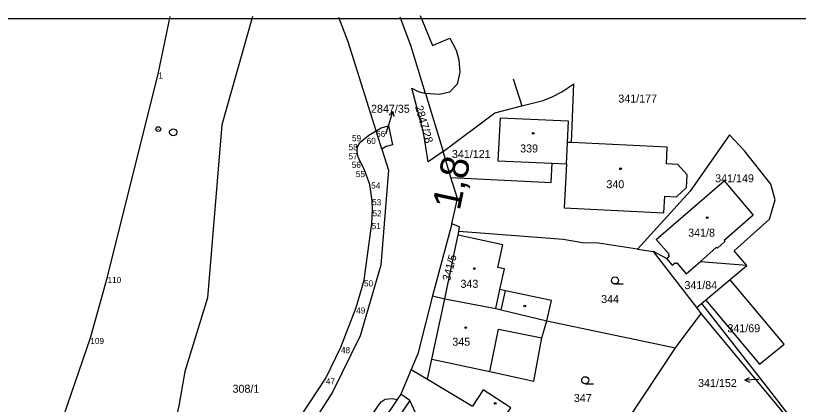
# Model space of a CAD drawing. Extents: x -558358 to -557517, y -1073785 to -1073189.
# Drawn here: x -558075.9 to -557909.7, y -1073271.9 to -1073189.5 of the extents above; entities that cross this region are included whole.
import ezdxf

# ---------------------------------------------------------------- set-up
doc = ezdxf.new("R2010")
doc.units = 0
for name, color, linetype in [('Hranice parcel', 7, 'Continuous'), ('Návěst místo trati', 7, 'Continuous'), ('Parcelní čísla', 7, 'Continuous'), ('Pop  PČ popisy', 7, 'Continuous'), ('Rozpiska_pole_1', 7, 'Continuous'), ('Svazek obcí údolí Desné', 7, 'Continuous'), ('Vnitřní kresba', 7, 'Continuous'), ('Vrstva 60', 7, 'Continuous'), ('Značky budov', 7, 'Continuous'), ('Značky kultur', 7, 'Continuous')]:
    doc.layers.add(name, color=color, linetype=linetype)

msp = doc.modelspace()

# ---------------------------------------------------------------- linework, layer by layer
at = {"layer": 'Hranice parcel'}
for p, q in [((-557970.23, -1073202.86), (-557968.43, -1073208.63)), ((-557957.84, -1073216.4), (-557957.38, -1073203.94)), ((-557990.44, -1073205.56), (-557988.88, -1073205.99)), ((-557988.88, -1073205.99), (-557985.13, -1073218.31)), ((-557985.87, -1073206.17), (-557988.88, -1073205.99)), ((-557974.16, -1073210.07), (-557968.43, -1073208.63)), ((-557985.13, -1073218.31), (-557974.16, -1073210.07)), ((-558000.9, -1073214.81), (-557999.34, -1073213.91)), ((-557999.34, -1073213.91), (-557998.27, -1073213.29)), ((-557998.11, -1073217.81), (-557999.34, -1073213.91)), ((-557924.3, -1073214.73), (-557932.67, -1073226.72)), ((-557997.23, -1073217.21), (-557998.11, -1073217.81)), ((-557958.95, -1073220.92), (-557958.74, -1073216.36)), ((-557957.84, -1073216.4), (-557958.74, -1073216.36)), ((-557985.13, -1073218.31), (-557988.34, -1073220.45)), ((-557983.46, -1073223.81), (-557985.13, -1073218.31)), ((-557961.95, -1073220.78), (-557958.95, -1073220.92)), ((-557932.67, -1073226.72), (-557943.85, -1073239.02)), ((-557983.29, -1073233.62), (-557987.36, -1073248.89)), ((-557981.96, -1073236.04), (-557981.79, -1073235.24)), ((-557943.85, -1073239.02), (-557940.47, -1073239.54)), ((-557931.28, -1073251.41), (-557940.47, -1073239.54)), ((-557937.69, -1073241), (-557940.47, -1073239.54)), ((-557920.64, -1073242.45), (-557930.56, -1073241.68)), ((-557930.24, -1073250.53), (-557920.64, -1073242.45)), ((-557987.36, -1073248.89), (-557984.8, -1073249.54)), ((-557931.28, -1073251.41), (-557930.24, -1073250.53)), ((-557935.78, -1073259.94), (-557930.32, -1073252.64)), ((-557930.32, -1073252.64), (-557931.28, -1073251.41)), ((-557909.08, -1073278.25), (-557930.32, -1073252.64)), ((-557963.13, -1073254.23), (-557935.78, -1073259.94)), ((-557954.2, -1073287.72), (-557935.78, -1073259.94)), ((-557991.89, -1073264.55), (-557994.13, -1073269.82)), ((-557991.89, -1073264.55), (-557988.45, -1073266.61)), ((-557988.45, -1073266.61), (-557978.88, -1073272.32)), ((-557994.86, -1073270.9), (-558022.09, -1073311.21)), ((-557995.96, -1073270.7), (-557994.86, -1073270.9)), ((-557994.13, -1073269.82), (-557994.86, -1073270.9)), ((-557992.18, -1073271.14), (-557994.13, -1073269.82)), ((-557990.25, -1073275.48), (-557992.18, -1073271.14))]:
    msp.add_line(p, q, dxfattribs=at)
for points in [[(-557990.03, -1073189.46), (-557987.35, -1073195.77), (-557983.68, -1073194.26), (-557982.33, -1073196.81), (-557981.76, -1073198.85), (-557981.57, -1073201.43), (-557982.14, -1073203.98), (-557983.75, -1073205.73), (-557985.87, -1073206.17)], [(-557988.88, -1073205.99), (-557991.98, -1073195.8), (-557994.22, -1073189.75)], [(-557968.43, -1073208.63), (-557963.9, -1073207.49), (-557961.96, -1073206.66), (-557959.95, -1073205.6), (-557957.38, -1073203.94)], [(-557988.34, -1073220.45), (-557989.32, -1073214.27), (-557991.8, -1073204.87), (-557990.44, -1073205.56)], [(-557958.74, -1073216.36), (-557958.53, -1073211.88), (-557973.01, -1073211.21), (-557973.48, -1073220.25), (-557961.95, -1073220.78)], [(-557998.27, -1073213.29), (-557996.72, -1073212.87), (-557995.91, -1073216.87), (-557997.23, -1073217.21)], [(-557920.64, -1073242.45), (-557923.35, -1073239.36), (-557915.81, -1073232.62), (-557914.61, -1073228.54), (-557915.51, -1073225.19), (-557921.13, -1073218.15), (-557924.3, -1073214.73)], [(-557958.95, -1073220.92), (-557959.44, -1073230.26), (-557938.22, -1073231.3), (-557938.05, -1073227.77), (-557935.56, -1073227.89), (-557933.42, -1073225.91), (-557933.29, -1073223.26), (-557935.3, -1073221.04), (-557937.72, -1073220.92), (-557937.55, -1073217.37), (-557957.84, -1073216.4)], [(-557998.11, -1073217.81), (-557996.7, -1073222.28), (-557998.38, -1073242.39), (-558002.78, -1073257.43), (-558008.62, -1073269.37), (-558024.06, -1073293.44), (-558032.02, -1073303.96), (-558033.31, -1073305.78)], [(-557983.46, -1073223.81), (-557962.16, -1073224.87), (-557961.95, -1073220.78)], [(-557983.29, -1073233.62), (-557982.1, -1073228.28), (-557983.46, -1073223.81)], [(-557937.69, -1073241), (-557937.08, -1073240.47), (-557937.28, -1073240.24), (-557937.09, -1073240.08), (-557939.85, -1073236.97), (-557925.45, -1073224.49), (-557919.26, -1073231.82), (-557925.44, -1073237.21), (-557925.27, -1073237.41), (-557926.88, -1073238.81), (-557927.05, -1073238.61), (-557930.56, -1073241.68)], [(-557981.79, -1073235.24), (-557981.67, -1073234.3), (-557983.29, -1073233.62)], [(-557943.85, -1073239.02), (-557952.12, -1073237.75), (-557955.56, -1073237.67), (-557959.65, -1073236.94), (-557981.79, -1073235.24)], [(-557984.8, -1073249.54), (-557982.04, -1073236.64), (-557981.96, -1073236.04)], [(-557963.13, -1073254.23), (-557962.1, -1073249.91), (-557971.91, -1073247.83), (-557973.07, -1073247.59), (-557972.12, -1073243.17), (-557973.48, -1073242.88), (-557972.48, -1073238.09), (-557981.96, -1073236.04)], [(-557937.69, -1073241), (-557936.45, -1073242.42), (-557935.84, -1073241.9), (-557935.68, -1073242.09), (-557935.49, -1073241.92), (-557933.49, -1073244.23), (-557930.56, -1073241.68)], [(-557912.73, -1073259.16), (-557924.17, -1073245.52), (-557929.3, -1073249.85), (-557917.91, -1073263.41), (-557912.73, -1073259.16)], [(-557987.36, -1073248.89), (-557990.48, -1073261.24), (-557991.89, -1073264.55)], [(-557984.8, -1073249.54), (-557973.92, -1073251.6), (-557972.79, -1073251.88), (-557963.13, -1073254.23)], [(-557930.24, -1073250.53), (-557916.49, -1073268.06), (-557909.46, -1073277.19)], [(-557988.45, -1073266.61), (-557987.54, -1073262.34), (-557975.19, -1073264.98), (-557965.84, -1073267.06), (-557964.16, -1073257.82), (-557963.13, -1073254.23)], [(-557973.02, -1073276.12), (-557970.72, -1073272.68), (-557976.62, -1073268.9), (-557978.88, -1073272.32)], [(-558021.55, -1073305.19), (-558007.79, -1073285.56), (-557998.91, -1073272.25), (-557998.29, -1073271.45), (-557997.41, -1073270.82), (-557995.96, -1073270.7)], [(-557992.18, -1073271.14), (-558017.7, -1073308.66), (-558015.75, -1073309.85), (-558004.08, -1073317.8), (-557996.67, -1073322.48), (-557993.43, -1073325.31), (-557988.49, -1073331.84)]]:
    msp.add_lwpolyline(points, dxfattribs=at)
at = {"layer": 'Návěst místo trati'}
msp.add_line((-558045.69, -1073213.53), (-558045.59, -1073213.53), dxfattribs=at)
for centre, radius in [((-558045.64, -1073213.53), 0.5), ((-558042.46, -1073214.22), 0.75)]:
    msp.add_circle(centre, radius, dxfattribs=at)
at = {"layer": 'Pop  PČ popisy'}
for p, q in [((-557996.68, -1073212.64), (-557995.8, -1073209.77)), ((-557995.8, -1073209.77), (-557996.57, -1073210.58)), ((-557995.8, -1073209.77), (-557995.62, -1073210.87)), ((-557997.26, -1073214.56), (-557996.68, -1073212.64)), ((-557921.05, -1073266.82), (-557920.07, -1073266.27)), ((-557918.05, -1073266.66), (-557921.05, -1073266.82)), ((-557921.05, -1073266.82), (-557920.02, -1073267.27))]:
    msp.add_line(p, q, dxfattribs=at)
at = {"layer": 'Rozpiska_pole_1'}
msp.add_line((-558357.53, -1073190.09), (-557516.53, -1073190.09), dxfattribs=at)
at = {"layer": 'Svazek obcí údolí Desné'}
for points in [[(-558082.18, -1073306.93), (-558073.77, -1073292.96), (-558066.53, -1073276.76), (-558060.05, -1073257.85), (-558056.4, -1073244.89), (-558045.6, -1073201.5), (-558043.07, -1073189.63)], [(-558025.59, -1073189.61), (-558032.09, -1073212.63), (-558035.15, -1073249.33), (-558039.97, -1073265.01), (-558041.24, -1073272.26), (-558045.55, -1073290.79), (-558055.77, -1073312.33), (-558066.64, -1073329.29), (-558067.37, -1073328.67), (-558071.91, -1073335.47), (-558071.45, -1073339.78), (-558072.38, -1073341.74), (-558078.52, -1073350.81)], [(-558066.74, -1073350.64), (-558065.9, -1073348.86), (-558061.08, -1073328.44), (-558060.65, -1073327.54), (-558046.7, -1073313.29), (-558030.4, -1073296.27), (-558015.33, -1073274.48), (-558010.02, -1073266.4), (-558006.82, -1073259.79), (-558003.58, -1073251.39), (-558001.93, -1073245.63), (-558000.3, -1073233.47), (-558000.14, -1073230.76), (-558000.21, -1073228.76), (-558000.67, -1073225.31), (-558001.93, -1073222.03), (-558003.18, -1073219.55), (-558003.41, -1073218.32), (-558003.28, -1073217.31), (-558002.8, -1073216.38), (-558000.9, -1073214.81), (-557999.34, -1073213.91), (-558005.3, -1073194.99), (-558007.29, -1073189.83)]]:
    msp.add_lwpolyline(points, dxfattribs=at)
at = {"layer": 'Vnitřní kresba'}
for p, q in [((-557973.92, -1073251.6), (-557973.07, -1073247.59)), ((-557972.79, -1073251.88), (-557971.91, -1073247.83)), ((-557987.54, -1073262.34), (-557984.8, -1073249.54)), ((-557975.19, -1073264.98), (-557973.4, -1073255.98)), ((-557973.4, -1073255.98), (-557964.16, -1073257.82))]:
    msp.add_line(p, q, dxfattribs=at)
at = {"layer": 'Vrstva 60'}
for p, q in [((-558045.6, -1073201.5), (-558045.6, -1073201.5)), ((-557999.34, -1073213.91), (-557999.34, -1073213.91)), ((-558000.9, -1073214.81), (-558000.9, -1073214.81)), ((-558003.28, -1073217.31), (-558003.28, -1073217.31)), ((-558002.8, -1073216.38), (-558002.8, -1073216.38)), ((-558003.41, -1073218.32), (-558003.41, -1073218.32)), ((-558003.18, -1073219.55), (-558003.18, -1073219.55)), ((-558001.93, -1073222.03), (-558001.93, -1073222.03)), ((-558000.67, -1073225.31), (-558000.67, -1073225.31)), ((-558000.21, -1073228.76), (-558000.21, -1073228.76)), ((-558000.14, -1073230.76), (-558000.14, -1073230.76)), ((-558000.3, -1073233.47), (-558000.3, -1073233.47)), ((-558056.4, -1073244.89), (-558056.4, -1073244.89)), ((-558001.93, -1073245.63), (-558001.93, -1073245.63)), ((-558003.58, -1073251.39), (-558003.58, -1073251.39)), ((-558060.05, -1073257.85), (-558060.05, -1073257.85)), ((-558006.82, -1073259.79), (-558006.82, -1073259.79)), ((-558010.02, -1073266.4), (-558010.02, -1073266.4))]:
    msp.add_line(p, q, dxfattribs=at)
at = {"layer": 'Značky budov'}
for centre in [(-557965.99, -1073214.44), (-557947.45, -1073221.95), (-557929.04, -1073232.33), (-557978.51, -1073243.13), (-557967.78, -1073251.08), (-557980.34, -1073255.67), (-557974.06, -1073271.72)]:
    msp.add_circle(centre, 0.175, dxfattribs=at)
at = {"layer": 'Značky kultur'}
for p, q in [((-557948.63, -1073246.4), (-557946.88, -1073246.4)), ((-557954.95, -1073267.58), (-557953.2, -1073267.58))]:
    msp.add_line(p, q, dxfattribs=at)
for centre in [(-557948.63, -1073245.65), (-557954.95, -1073266.83)]:
    msp.add_circle(centre, 0.75, dxfattribs=at)

# ---------------------------------------------------------------- texts
at = {"layer": 'Návěst místo trati'}
msp.add_text('1,8', height=6, rotation=77.8693, dxfattribs=at).set_placement((-557981.63, -1073230.98))
at = {"layer": 'Parcelní čísla'}
for s, p in [('341/177', (-557947.92, -1073207.91)), ('2847/35', (-558000.44, -1073210.07)), ('339', (-557968.77, -1073218.49)), ('341/121', (-557983.26, -1073219.67)), ('340', (-557950.45, -1073226.08)), ('341/149', (-557927.35, -1073224.83)), ('341/8', (-557933.08, -1073236.37)), ('343', (-557981.45, -1073247.22)), ('341/84', (-557933.88, -1073247.5)), ('344', (-557951.57, -1073250.45)), ('341/69', (-557924.75, -1073256.65)), ('345', (-557983.18, -1073259.51)), ('341/152', (-557930.98, -1073268.27)), ('308/1', (-558029.85, -1073269.49)), ('347', (-557957.36, -1073271.45))]:
    msp.add_text(s, height=1.7, dxfattribs=at).set_placement(p)
for s, rotation, p in [('2847/28', 286, (-557991.1, -1073208.79)), ('341/5', 75, (-557983.69, -1073245.9))]:
    msp.add_text(s, height=1.7, rotation=rotation, dxfattribs=at).set_placement(p)
at = {"layer": 'Vrstva 60'}
for s, p in [('1', (-558045.6, -1073202.8)), ('66', (-557999.34, -1073215.21)), ('59', (-558004.49, -1073216.11)), ('60', (-558001.36, -1073216.69)), ('58', (-558005.2, -1073218.02)), ('57', (-558005.23, -1073219.95)), ('56', (-558004.53, -1073221.77)), ('55', (-558003.66, -1073223.73)), ('54', (-558000.4, -1073226.16)), ('53', (-558000.21, -1073229.7)), ('52', (-558000.14, -1073232.06)), ('51', (-558000.3, -1073234.77)), ('110', (-558056.4, -1073246.19)), ('50', (-558001.93, -1073246.93)), ('49', (-558003.58, -1073252.69)), ('109', (-558060.05, -1073259.15)), ('48', (-558006.82, -1073261.09)), ('47', (-558010.02, -1073267.7))]:
    msp.add_text(s, height=1.3, dxfattribs=at).set_placement(p)

doc.saveas('drawing.dxf')
